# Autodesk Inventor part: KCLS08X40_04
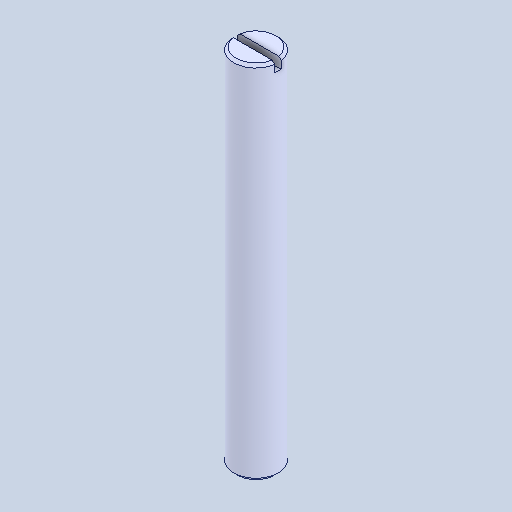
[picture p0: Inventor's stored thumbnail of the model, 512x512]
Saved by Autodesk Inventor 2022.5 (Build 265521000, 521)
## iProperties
Created: 2024-08
Part Number: KCLS08X40_04
Material: 一般
Document SubType Name: Modeling
Designer: ImaoCorp
Density: 1 g/cm^3
Appearance: 既定
Author: ImaoCorp
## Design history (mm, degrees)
feature "KCLS08X40_04"
node "ソリッド1"
